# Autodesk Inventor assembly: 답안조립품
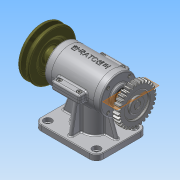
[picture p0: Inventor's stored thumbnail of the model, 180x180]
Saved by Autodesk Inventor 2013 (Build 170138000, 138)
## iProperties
Created: 2015-09
Part Number: 답안조립품
Document SubType Name: Assembly
Designer: Administrator
Mass: 2251.17 g
Surface Area: 1633.51 cm^2
Volume: 528.515 cm^3
Density: 4.25943 g/cm^3
Author: Administrator
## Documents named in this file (17)
- C:\Users\Administrator\Desktop\350908V1020\답안조립품.iam
- C:\Users\Administrator\Desktop\350908V1020\본체.ipt
- C:\Users\Administrator\Desktop\350908V1020\M3x0.5x8.ipt
- C:\Users\Administrator\Desktop\350908V1020\M4x0.5x14.ipt
- C:\Users\Administrator\Desktop\350908V1020\V-벨트풀리.ipt
- C:\Users\Administrator\Desktop\350908V1020\가변스프링.ipt
- C:\Users\Administrator\Desktop\350908V1020\뒤커버.ipt
- C:\Users\Administrator\Desktop\350908V1020\멈춤나사.ipt
- C:\Users\Administrator\Desktop\350908V1020\베어링 6201.ipt
- C:\Users\Administrator\Desktop\350908V1020\베어링 6202.ipt
- C:\Users\Administrator\Desktop\350908V1020\본체 커버.ipt
- C:\Users\Administrator\Desktop\350908V1020\스퍼기어.ipt
- C:\Users\Administrator\Desktop\350908V1020\슬라이드.ipt
- C:\Users\Administrator\Desktop\350908V1020\앞커버.ipt
- C:\Users\Administrator\Desktop\350908V1020\오일실.ipt
- C:\Users\Administrator\Desktop\350908V1020\키4x4.ipt
- C:\Users\Administrator\Desktop\350908V1020\편심축.ipt
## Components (14 placed, 4 different names)
1. M4x0.5x14:1
2. V-벨트풀리:1 — 플러쉬:1, 각도:1
3. 가변스프링:1
4. M4x0.5x14:2
5. M4x0.5x14:3
6. M4x0.5x14:4
7. M3x0.5x8:1
8. M3x0.5x8:3
9. M3x0.5x8:4
10. M3x0.5x8:5
11. M3x0.5x8:2
12. M3x0.5x8:6
13. M3x0.5x8:7
14. M3x0.5x8:8
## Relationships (2: Flush 1, Angle 1)
- 플러쉬:1 [Flush]: V-벨트풀리:1
- 각도:1 [Angle]: V-벨트풀리:1
